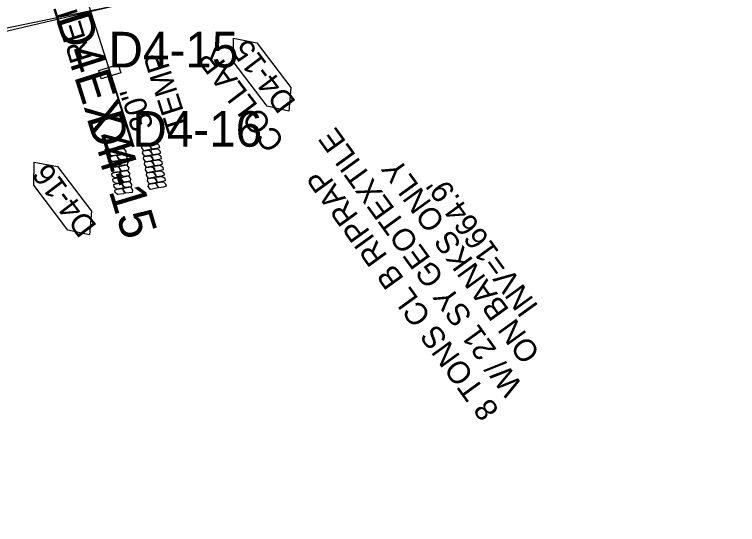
# Model space of a CAD drawing. Extents: x 465700 to 483515, y 488970 to 507540.
# Drawn here: x 476504.7 to 476667, y 500890 to 501004.5 of the extents above; entities that cross this region are included whole.
import ezdxf

# ---------------------------------------------------------------- set-up
doc = ezdxf.new("R2010")
doc.units = 0
for name, color, linetype in [('Exist Plan Preparation Watershed Blue', 7, 'Continuous'), ('Prop Drainage Structure Box Number Symbol CELL', 7, 'Continuous'), ('Prop Drainage Structure Pipe Collar CELL', 7, 'Continuous'), ('Prop Drainage Structure Pipe Collar Label', 7, 'Continuous'), ('Prop Drainage Structure Pipe RCP 30in Class III', 7, 'Continuous'), ('Prop Drainage Structure Pipe RCP 30in Class III Label', 7, 'Continuous'), ('Prop Drainage Structure Tops and Inverts LABEL', 7, 'Continuous'), ('Prop Erosion Rip Rap Pad at Outlet Label', 7, 'Continuous'), ('Prop Erosion Rip Rap Pad Outlet for Jurisdictional Stream CELL', 7, 'Continuous'), ('Scratch_Level_8', 7, 'Continuous')]:
    doc.layers.add(name, color=color, linetype=linetype)

msp = doc.modelspace()

# ---------------------------------------------------------------- linework, layer by layer
at = {"layer": 'Exist Plan Preparation Watershed Blue'}
for points in [[(476921.2, 501693.96), (476873.97, 501665.49), (476797.54, 501630.58), (476778.04, 501586.57), (476684.08, 501524.02), (476617.13, 501430.2), (476608.09, 501344.67), (476632.2, 501297.34), (476652.85, 501202.84), (476684.48, 501113.94), (476686.07, 501079.86), (476666.3, 501048.93), (476630.01, 501028.21), (476577.87, 501021.26), (476528.03, 501006.59), (476466.6, 500992.22), (476420.26, 500966.99), (476486.96, 500889.51), (476555.03, 500816.27), (476625.62, 500745.44), (476698.65, 500677.13), (476726.48, 500652.21), (476834.31, 500555.52), (476965.29, 500641)], [(476652.85, 501202.84), (476684.48, 501113.94), (476686.07, 501079.86), (476666.3, 501048.93), (476630.01, 501028.21), (476577.87, 501021.26), (476528.03, 501006.59), (476497.08, 501000.21), (476482.89, 500996.49), (476466.6, 500992.22), (476455.71, 500986.82), (476443.7, 500979.93), (476439.14, 500977.28), (476420.26, 500966.99), (476358.7, 501042.92), (476298.67, 501122.89), (476241.47, 501204.91)]]:
    msp.add_lwpolyline(points, dxfattribs=at)
at = {"layer": 'Prop Drainage Structure Box Number Symbol CELL'}
for points in [[(476561.37, 500983.89), (476553.76, 500993.94), (476553.86, 500999.17), (476559.1, 500998.18), (476566.71, 500988.13), (476566.27, 500982.78), (476561.37, 500983.89)], [(476516.62, 500956.1), (476509.02, 500966.15), (476509.12, 500971.37), (476514.35, 500970.38), (476521.96, 500960.33), (476521.52, 500954.99), (476516.62, 500956.1)]]:
    msp.add_lwpolyline(points, dxfattribs=at)
at = {"layer": 'Prop Drainage Structure Pipe Collar CELL'}
msp.add_line((476525.77, 500992.62), (476525.77, 500992.62), dxfattribs=at)
msp.add_line((476525.77, 500992.62), (476525.77, 500992.62), dxfattribs=at)
msp.add_lwpolyline([(476525.55, 500993.36), (476525.77, 500992.62), (476527.94, 500993.28), (476528.51, 500991.38), (476524.16, 500990.08), (476523.59, 500991.97), (476523.59, 500991.97), (476525.77, 500992.62)], dxfattribs=at)
msp.add_lwpolyline([(476527.94, 500993.28), (476528.51, 500991.38), (476524.16, 500990.08), (476523.59, 500991.97)], close=True, dxfattribs=at)
at = {"layer": 'Prop Drainage Structure Pipe RCP 30in Class III'}
msp.add_line((476525.76, 500992.65), (476531.47, 500974.83), dxfattribs=at)
at = {"layer": 'Prop Erosion Rip Rap Pad Outlet for Jurisdictional Stream CELL'}
msp.add_line((476531.14, 500974.82), (476531.14, 500974.82), dxfattribs=at)
msp.add_line((476531.14, 500974.82), (476531.14, 500974.82), dxfattribs=at)
for points in [[(476527.54, 500974.09), (476528.12, 500974.26), (476529.18, 500974.44), (476529.65, 500973.77), (476529.57, 500973.24), (476528.15, 500973.07), (476527.64, 500973.49), (476527.54, 500974.09)], [(476535.33, 500974.26), (476534.75, 500974.09), (476533.69, 500973.9), (476533.22, 500974.58), (476533.3, 500975.11), (476534.72, 500975.27), (476535.23, 500974.84), (476535.33, 500974.26)], [(476537.2, 500974.59), (476536.62, 500974.41), (476535.56, 500974.23), (476535.09, 500974.91), (476535.17, 500975.43), (476536.59, 500975.6), (476537.1, 500975.17), (476537.2, 500974.59)], [(476537.41, 500973.35), (476536.83, 500973.17), (476535.77, 500972.98), (476535.3, 500973.68), (476535.39, 500974.2), (476536.81, 500974.35), (476537.31, 500973.92), (476537.41, 500973.35)], [(476525.67, 500973.76), (476526.25, 500973.94), (476527.31, 500974.12), (476527.78, 500973.44), (476527.69, 500972.92), (476526.28, 500972.75), (476525.77, 500973.17), (476525.67, 500973.76)], [(476525.88, 500972.52), (476526.46, 500972.71), (476527.52, 500972.89), (476528, 500972.2), (476527.91, 500971.68), (476526.49, 500971.52), (476525.98, 500971.94), (476525.88, 500972.52)], [(476527.76, 500972.84), (476528.33, 500973.03), (476529.39, 500973.21), (476529.87, 500972.52), (476529.78, 500972), (476528.36, 500971.84), (476527.86, 500972.26), (476527.76, 500972.84)], [(476535.54, 500973.03), (476534.96, 500972.84), (476533.9, 500972.66), (476533.43, 500973.35), (476533.52, 500973.87), (476534.93, 500974.03), (476535.44, 500973.6), (476535.54, 500973.03)], [(476535.75, 500971.79), (476535.18, 500971.6), (476534.12, 500971.42), (476533.64, 500972.11), (476533.73, 500972.63), (476535.15, 500972.79), (476535.65, 500972.37), (476535.75, 500971.79)], [(476537.63, 500972.11), (476537.05, 500971.92), (476535.99, 500971.74), (476535.52, 500972.43), (476535.6, 500972.95), (476537.02, 500973.11), (476537.53, 500972.69), (476537.63, 500972.11)], [(476526.1, 500971.27), (476526.68, 500971.46), (476527.74, 500971.65), (476528.21, 500970.95), (476528.12, 500970.43), (476526.7, 500970.27), (476526.2, 500970.71), (476526.1, 500971.27)], [(476527.97, 500971.6), (476528.55, 500971.79), (476529.61, 500971.97), (476530.08, 500971.28), (476529.99, 500970.75), (476528.58, 500970.6), (476528.07, 500971.03), (476527.97, 500971.6)], [(476535.97, 500970.54), (476535.39, 500970.37), (476534.33, 500970.18), (476533.86, 500970.86), (476533.95, 500971.39), (476535.36, 500971.56), (476535.87, 500971.13), (476535.97, 500970.54)], [(476537.84, 500970.87), (476537.26, 500970.69), (476536.2, 500970.51), (476535.73, 500971.19), (476535.82, 500971.71), (476537.23, 500971.88), (476537.74, 500971.46), (476537.84, 500970.87)], [(476526.31, 500970.04), (476526.89, 500970.22), (476527.95, 500970.4), (476528.42, 500969.72), (476528.34, 500969.2), (476526.92, 500969.03), (476526.41, 500969.46), (476526.31, 500970.04)], [(476528.18, 500970.37), (476528.76, 500970.54), (476529.82, 500970.72), (476530.3, 500970.05), (476530.21, 500969.52), (476528.79, 500969.35), (476528.28, 500969.79), (476528.18, 500970.37)], [(476528.4, 500969.13), (476528.98, 500969.31), (476530.04, 500969.49), (476530.51, 500968.81), (476530.42, 500968.29), (476529, 500968.12), (476528.5, 500968.54), (476528.4, 500969.13)], [(476536.18, 500969.31), (476535.6, 500969.14), (476534.54, 500968.95), (476534.07, 500969.63), (476534.16, 500970.15), (476535.57, 500970.32), (476536.08, 500969.89), (476536.18, 500969.31)], [(476538.05, 500969.64), (476537.47, 500969.46), (476536.42, 500969.28), (476535.94, 500969.96), (476536.03, 500970.48), (476537.45, 500970.65), (476537.95, 500970.21), (476538.05, 500969.64)], [(476526.53, 500968.81), (476527.1, 500968.99), (476528.16, 500969.17), (476528.64, 500968.49), (476528.55, 500967.97), (476527.13, 500967.8), (476526.63, 500968.22), (476526.53, 500968.81)], [(476526.74, 500967.57), (476527.32, 500967.76), (476528.38, 500967.94), (476528.85, 500967.25), (476528.76, 500966.72), (476527.34, 500966.57), (476526.84, 500966.99), (476526.74, 500967.57)], [(476528.61, 500967.89), (476529.19, 500968.08), (476530.25, 500968.26), (476530.72, 500967.57), (476530.64, 500967.05), (476529.22, 500966.89), (476528.71, 500967.31), (476528.61, 500967.89)], [(476536.39, 500968.08), (476535.82, 500967.89), (476534.76, 500967.71), (476534.28, 500968.4), (476534.37, 500968.92), (476535.79, 500969.08), (476536.3, 500968.65), (476536.39, 500968.08)], [(476536.61, 500966.84), (476536.03, 500966.65), (476534.97, 500966.46), (476534.5, 500967.16), (476534.59, 500967.68), (476536, 500967.84), (476536.51, 500967.41), (476536.61, 500966.84)], [(476538.27, 500968.4), (476537.69, 500968.21), (476536.63, 500968.03), (476536.16, 500968.72), (476536.24, 500969.25), (476537.66, 500969.4), (476538.17, 500968.97), (476538.27, 500968.4)], [(476538.48, 500967.16), (476537.9, 500966.97), (476536.85, 500966.79), (476536.37, 500967.48), (476536.46, 500968), (476537.88, 500968.16), (476538.38, 500967.74), (476538.48, 500967.16)], [(476526.96, 500966.32), (476527.53, 500966.51), (476528.59, 500966.69), (476529.07, 500966), (476528.98, 500965.48), (476527.56, 500965.32), (476527.05, 500965.76), (476526.96, 500966.32)], [(476528.83, 500966.65), (476529.4, 500966.83), (476530.46, 500967.02), (476530.94, 500966.33), (476530.85, 500965.8), (476529.43, 500965.65), (476528.93, 500966.08), (476528.83, 500966.65)], [(476536.82, 500965.59), (476536.24, 500965.42), (476535.19, 500965.23), (476534.71, 500965.91), (476534.8, 500966.43), (476536.22, 500966.6), (476536.72, 500966.18), (476536.82, 500965.59)], [(476538.7, 500965.92), (476538.12, 500965.74), (476537.06, 500965.56), (476536.59, 500966.24), (476536.67, 500966.76), (476538.09, 500966.93), (476538.59, 500966.51), (476538.7, 500965.92)], [(476527.17, 500965.09), (476527.75, 500965.27), (476528.81, 500965.45), (476529.28, 500964.77), (476529.19, 500964.25), (476527.77, 500964.08), (476527.27, 500964.51), (476527.17, 500965.09)], [(476529.04, 500965.41), (476529.62, 500965.59), (476530.68, 500965.77), (476531.15, 500965.09), (476531.06, 500964.57), (476529.65, 500964.4), (476529.14, 500964.84), (476529.04, 500965.41)]]:
    msp.add_lwpolyline(points, dxfattribs=at)
at = {"layer": 'Scratch_Level_8'}
for p, q in [((476517.23, 501019.61), (476525.77, 500992.62)), ((476525.77, 500992.62), (476531.14, 500974.82))]:
    msp.add_line(p, q, dxfattribs=at)

# ---------------------------------------------------------------- texts
at = {"layer": 'Prop Drainage Structure Box Number Symbol CELL'}
for s, p in [('D4-15', (476568.02, 500984.87)), ('D4-16', (476523.33, 500957))]:
    msp.add_text(s, height=5, rotation=127.1208, dxfattribs=at).set_placement(p)
at = {"layer": 'Prop Drainage Structure Pipe Collar Label'}
for s, rotation, p in [('RETAIN', 107.5926, (476522.15, 500994.59)), ('COLLAR', 127.1236, (476565.52, 500976.06))]:
    msp.add_text(s, height=5, rotation=rotation, dxfattribs=at).set_placement(p)
at = {"layer": 'Prop Drainage Structure Pipe RCP 30in Class III Label'}
for s, p in [('TEMP', (476543.93, 500978.95)), ('30" ', (476535.95, 500979.3))]:
    msp.add_text(s, height=5, rotation=107.7533, dxfattribs=at).set_placement(p)
at = {"layer": 'Prop Drainage Structure Tops and Inverts LABEL'}
msp.add_text("INV=1664.9'", height=5, rotation=125.9074, dxfattribs=at).set_placement((476622.44, 500938.97))
at = {"layer": 'Prop Erosion Rip Rap Pad at Outlet Label'}
for s, p in [('W/ 21 SY GEOTEXTILE', (476618.94, 500921.1)), ('ON BANKS ONLY', (476622.84, 500928.5)), ('8 TONS CL B RIPRAP', (476613.61, 500915.67))]:
    msp.add_text(s, height=5, rotation=125.9074, dxfattribs=at).set_placement(p)
at = {"layer": 'Scratch_Level_8'}
for s, rotation, p in [('D4EX4', 287.5659, (476513.87, 501003.7)), ('D4-15', 286.8041, (476520.8, 500981.41))]:
    msp.add_text(s, height=8, rotation=rotation, dxfattribs=at).set_placement(p)
for s, p in [('D4-15', (476525.77, 500992.62)), ('D4-16', (476531.14, 500974.82))]:
    msp.add_text(s, height=8, dxfattribs=at).set_placement(p)

doc.saveas('drawing.dxf')
